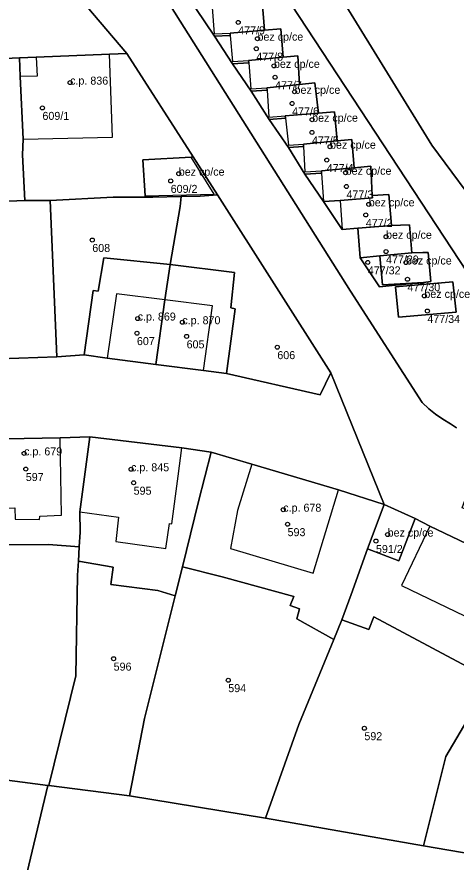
# Model space of a CAD drawing. Extents: x -878211 to -870363, y -1058464 to -1052522.
# Drawn here: x -874333.2 to -874278.3, y -1056644.7 to -1056539.1 of the extents above; entities that cross this region are included whole.
import ezdxf

# ---------------------------------------------------------------- set-up
doc = ezdxf.new("R2010")
doc.units = 0
for name, color, linetype in [('Vrstva 50', 7, 'Continuous'), ('Vrstva 51', 7, 'Continuous'), ('Vrstva 52', 7, 'Continuous')]:
    doc.layers.add(name, color=color, linetype=linetype)

msp = doc.modelspace()

# ---------------------------------------------------------------- linework, layer by layer
at = {"layer": 'Vrstva 50'}
for centre in [(-874305.53, -1056539.80994), (-874303.12, -1056541.83994), (-874303.27, -1056543.09994), (-874301.06, -1056545.23994), (-874326.54, -1056547.32994), (-874300.92, -1056546.66994), (-874298.49, -1056548.47994), (-874330, -1056550.49994), (-874298.79, -1056549.93994), (-874296.29, -1056551.96994), (-874296.31, -1056553.55994), (-874294.05, -1056555.33994), (-874294.46, -1056557.00994), (-874312.96, -1056558.70994), (-874292.1, -1056558.58994), (-874313.97, -1056559.61994), (-874292, -1056560.30994), (-874289.21, -1056562.53994), (-874289.58, -1056563.86994), (-874323.77, -1056566.99994), (-874287.05, -1056566.58994), (-874287.05, -1056568.43994), (-874289.33, -1056569.79994), (-874284.57, -1056569.80994), (-874284.37, -1056571.89994), (-874282.26, -1056573.97994), (-874281.89, -1056575.86994), (-874318.09, -1056576.80994), (-874312.51, -1056577.26994), (-874318.19, -1056578.63994), (-874311.98, -1056579.03994), (-874300.64, -1056580.38994), (-874332.29, -1056593.65994), (-874332.08, -1056595.61994), (-874318.92, -1056595.63994), (-874318.6, -1056597.32994), (-874299.9, -1056600.68994), (-874299.36, -1056602.50994), (-874286.85, -1056603.79994), (-874288.31, -1056604.60994), (-874321.1, -1056619.30994), (-874306.77, -1056621.99994), (-874289.76, -1056627.99994)]:
    msp.add_circle(centre, 0.25, dxfattribs=at)
at = {"layer": 'Vrstva 51'}
for points in [[(-874435.23, -1056399.98), (-874420.12, -1056431.27), (-874417.67, -1056433.88), (-874411.69, -1056441.25), (-874402.98, -1056437.26), (-874396.18, -1056442.04), (-874393, -1056445.85), (-874370.58, -1056484.27), (-874355.24, -1056493.16), (-874347.2, -1056502.65), (-874344.62, -1056505.87), (-874336.73, -1056517.84), (-874326.2, -1056533.69), (-874326.13, -1056535.82), (-874319.45, -1056543.71), (-874311.18, -1056556.62)], [(-874374.27, -1056421.51), (-874364.19, -1056438.09), (-874334.57, -1056483.76), (-874308.37, -1056523.13), (-874269.31, -1056582.53)], [(-874274.54, -1056564.3), (-874281.34, -1056555.14), (-874302.81, -1056520.2), (-874326.64, -1056483.24), (-874328.23, -1056479.69), (-874334.9, -1056469.3), (-874347.77, -1056449.81), (-874358.83, -1056429.38), (-874355.4, -1056424.52)], [(-874269.31, -1056582.53), (-874308.37, -1056523.13), (-874334.57, -1056483.76), (-874364.19, -1056438.09), (-874370.01, -1056432.66), (-874371.12, -1056433.98), (-874373.43, -1056437.7), (-874374.51, -1056440.86), (-874365.05, -1056457.11), (-874357.66, -1056452.3), (-874349.38, -1056465.01), (-874349.37, -1056465.41), (-874354.76, -1056465.71), (-874356.24, -1056463.46), (-874359.52, -1056465.6), (-874291.5, -1056573.37), (-874282.53, -1056587.29), (-874281.7, -1056588.08), (-874280.88, -1056588.76), (-874279.96, -1056589.37), (-874279, -1056589.96), (-874278.23, -1056590.45)], [(-874278.23, -1056590.45), (-874279, -1056589.96), (-874279.96, -1056589.37), (-874280.88, -1056588.76), (-874281.7, -1056588.08), (-874282.53, -1056587.29), (-874291.5, -1056573.37), (-874359.52, -1056465.6)], [(-874302.55, -1056537.15), (-874302.23, -1056540.78), (-874300.2, -1056540.6), (-874299.92, -1056544.15), (-874298.09, -1056544), (-874297.87, -1056547.57), (-874295.97, -1056547.37), (-874295.5, -1056551.13), (-874293.48, -1056550.98), (-874293.17, -1056554.61), (-874291.33, -1056554.45), (-874291.04, -1056557.96), (-874288.96, -1056557.79), (-874288.77, -1056561.43), (-874286.7, -1056561.3), (-874286.38, -1056565.2), (-874284.11, -1056565.08), (-874283.82, -1056568.61), (-874282.45, -1056568.57), (-874281.8, -1056568.54), (-874281.45, -1056572.2), (-874282.39, -1056572.3), (-874285.88, -1056572.65), (-874287.87, -1056572.83), (-874290.29, -1056569.21), (-874290.58, -1056565.53), (-874292.55, -1056565.68), (-874294.87, -1056562.2), (-874297.2, -1056558.77), (-874299.23, -1056555.44), (-874301.67, -1056551.94), (-874303.92, -1056548.41), (-874306.24, -1056544.98), (-874308.51, -1056541.53), (-874310.84, -1056538.07)], [(-874311.18, -1056556.62), (-874308.13, -1056561.37), (-874293.97, -1056583.61), (-874287.3, -1056600.03), (-874283.43, -1056601.8), (-874281.56, -1056602.75), (-874271.47, -1056607.59), (-874266.82, -1056609.82), (-874264.4, -1056605.69), (-874277.53, -1056600.45), (-874276.7, -1056598.17), (-874263.18, -1056603.62), (-874260.74, -1056604.6), (-874243.35, -1056611.56), (-874228.09, -1056617.62), (-874226.05, -1056618.95), (-874224.66, -1056621.19), (-874224.22, -1056623.66), (-874227.16, -1056650.06)], [(-874339.1, -1056591.92), (-874327.78, -1056591.72), (-874324.06, -1056591.59), (-874312.58, -1056592.98), (-874308.91, -1056593.5), (-874303.84, -1056595), (-874293.01, -1056598.21), (-874287.3, -1056600.03), (-874293.97, -1056583.61), (-874295.29, -1056586.33), (-874307.01, -1056583.66), (-874309.88, -1056583.3), (-874315.83, -1056582.54), (-874321.9, -1056581.74), (-874324.8, -1056581.36), (-874328.19, -1056581.59), (-874335.36, -1056581.83)]]:
    msp.add_lwpolyline(points, dxfattribs=at)
for points in [[(-874271.27, -1056564.06), (-874271.86, -1056562.49), (-874272.17, -1056562.59), (-874274.2, -1056556.7), (-874274.34, -1056556.7), (-874275.7, -1056552.64), (-874265.35, -1056549.02), (-874263.86, -1056553.37), (-874265.09, -1056548.95), (-874273.55, -1056514.26), (-874288.39, -1056517.65), (-874302.81, -1056520.2), (-874281.34, -1056555.14), (-874274.54, -1056564.3)], [(-874330.78, -1056544.15), (-874321.63, -1056543.78), (-874319.45, -1056543.71), (-874326.13, -1056535.82), (-874348.38, -1056536.81), (-874364.21, -1056536.96), (-874384.19, -1056537.86), (-874403.14, -1056538.55), (-874419.92, -1056539.28), (-874440.04, -1056540.15), (-874428.62, -1056547.76), (-874417.19, -1056547.36), (-874405.53, -1056546.89), (-874402.16, -1056546.76), (-874383.9, -1056546.09), (-874373.1, -1056545.73), (-874365.49, -1056545.45), (-874362.2, -1056545.35), (-874355.93, -1056545.07), (-874349.64, -1056544.84), (-874344.53, -1056544.62), (-874343.6, -1056544.63), (-874336.58, -1056544.39), (-874332.88, -1056544.22)], [(-874308.79, -1056537.93), (-874310.84, -1056538.07), (-874308.51, -1056541.53), (-874306.54, -1056541.45), (-874306.55, -1056541.15), (-874302.23, -1056540.78), (-874302.55, -1056537.15), (-874304.61, -1056537.26), (-874308.81, -1056537.63)], [(-874302.23, -1056540.78), (-874306.55, -1056541.15), (-874306.54, -1056541.45), (-874308.51, -1056541.53), (-874306.24, -1056544.98), (-874304.22, -1056544.87), (-874304.23, -1056544.57), (-874299.92, -1056544.15), (-874300.2, -1056540.6)], [(-874317.18, -1056561.49), (-874317.46, -1056556.97), (-874311.43, -1056556.63), (-874311.18, -1056556.62), (-874319.45, -1056543.71), (-874321.63, -1056543.78), (-874330.78, -1056544.15), (-874332.88, -1056544.22), (-874332.77, -1056546.58), (-874332.4, -1056554.4), (-874332.5, -1056556.36), (-874332.19, -1056562.08), (-874329.05, -1056562.05), (-874321.16, -1056561.66), (-874317.17, -1056561.66)], [(-874332.4, -1056554.4), (-874332.77, -1056546.58), (-874332.88, -1056544.22), (-874336.58, -1056544.39), (-874343.6, -1056544.63), (-874344.53, -1056544.62), (-874344.44, -1056551.39), (-874344.34, -1056558.31), (-874344.29, -1056562.58), (-874342.16, -1056562.49), (-874332.19, -1056562.08), (-874332.5, -1056556.36)], [(-874304.23, -1056544.57), (-874304.22, -1056544.87), (-874306.24, -1056544.98), (-874303.92, -1056548.41), (-874301.93, -1056548.27), (-874301.95, -1056547.97), (-874297.87, -1056547.57), (-874298.09, -1056544), (-874299.92, -1056544.15)], [(-874297.87, -1056547.57), (-874301.95, -1056547.97), (-874301.93, -1056548.27), (-874303.92, -1056548.41), (-874301.67, -1056551.94), (-874299.62, -1056551.78), (-874299.64, -1056551.48), (-874295.5, -1056551.13), (-874295.97, -1056547.37)], [(-874299.64, -1056551.48), (-874299.62, -1056551.78), (-874301.67, -1056551.94), (-874299.23, -1056555.44), (-874297.38, -1056555.33), (-874297.39, -1056555.03), (-874293.17, -1056554.61), (-874293.48, -1056550.98), (-874295.5, -1056551.13)], [(-874297.38, -1056555.33), (-874299.23, -1056555.44), (-874297.2, -1056558.77), (-874295.11, -1056558.66), (-874295.12, -1056558.36), (-874291.04, -1056557.96), (-874291.33, -1056554.45), (-874293.17, -1056554.61), (-874297.39, -1056555.03)], [(-874308.13, -1056561.37), (-874311.18, -1056556.62), (-874311.43, -1056556.63), (-874317.46, -1056556.97), (-874317.18, -1056561.49), (-874317.17, -1056561.66), (-874316.19, -1056561.66), (-874312.65, -1056561.57), (-874310.3, -1056561.5)], [(-874291.04, -1056557.96), (-874295.12, -1056558.36), (-874295.11, -1056558.66), (-874297.2, -1056558.77), (-874294.87, -1056562.2), (-874292.8, -1056562.06), (-874288.75, -1056561.73), (-874288.77, -1056561.43), (-874288.96, -1056557.79)], [(-874321.16, -1056561.66), (-874329.05, -1056562.05), (-874328.19, -1056581.59), (-874324.8, -1056581.36), (-874323.66, -1056573.29), (-874323.03, -1056573.38), (-874322.34, -1056569.23), (-874314.03, -1056570.04), (-874312.78, -1056562.81), (-874312.65, -1056561.57), (-874316.19, -1056561.66), (-874317.17, -1056561.66)], [(-874308.13, -1056561.37), (-874310.3, -1056561.5), (-874312.65, -1056561.57), (-874312.78, -1056562.81), (-874314.03, -1056570.04), (-874305.99, -1056571.06), (-874306.45, -1056575.48), (-874305.89, -1056575.58), (-874307.01, -1056583.66), (-874295.29, -1056586.33), (-874293.97, -1056583.61)], [(-874286.38, -1056565.2), (-874286.7, -1056561.3), (-874288.77, -1056561.43), (-874288.75, -1056561.73), (-874292.8, -1056562.06), (-874294.87, -1056562.2), (-874292.55, -1056565.68), (-874290.58, -1056565.53)], [(-874329.05, -1056562.05), (-874332.19, -1056562.08), (-874342.16, -1056562.49), (-874341.76, -1056569.18), (-874341.57, -1056573.8), (-874341.5, -1056581.93), (-874335.36, -1056581.83), (-874328.19, -1056581.59)], [(-874283.82, -1056568.61), (-874284.11, -1056565.08), (-874286.38, -1056565.2), (-874290.58, -1056565.53), (-874290.29, -1056569.21), (-874287.84, -1056568.98)], [(-874324.8, -1056581.36), (-874321.9, -1056581.74), (-874315.83, -1056582.54), (-874314.72, -1056574.46), (-874314.03, -1056570.04), (-874322.34, -1056569.23), (-874323.03, -1056573.38), (-874323.66, -1056573.29)], [(-874287.84, -1056568.98), (-874290.29, -1056569.21), (-874287.87, -1056572.83), (-874285.88, -1056572.65), (-874282.39, -1056572.3), (-874287.51, -1056572.58)], [(-874282.39, -1056572.3), (-874281.45, -1056572.2), (-874281.8, -1056568.54), (-874282.45, -1056568.57), (-874283.82, -1056568.61), (-874287.84, -1056568.98), (-874287.51, -1056572.58)], [(-874314.03, -1056570.04), (-874314.72, -1056574.46), (-874315.83, -1056582.54), (-874309.88, -1056583.3), (-874307.01, -1056583.66), (-874305.89, -1056575.58), (-874306.45, -1056575.48), (-874305.99, -1056571.06)], [(-874285.48, -1056576.64), (-874278.3, -1056576.01), (-874278.7, -1056572.22), (-874285.88, -1056572.85)], [(-874285.48, -1056576.64), (-874285.88, -1056572.85), (-874278.7, -1056572.22), (-874278.3, -1056576.01)], [(-874325.4, -1056605.34), (-874325.28, -1056603.5), (-874325.31, -1056600.96), (-874324.06, -1056591.59), (-874327.78, -1056591.72), (-874339.1, -1056591.92), (-874342.02, -1056591.97), (-874341.46, -1056603.51), (-874341.43, -1056606.57), (-874338.56, -1056606.64), (-874338.51, -1056605.07), (-874329.26, -1056605.05)], [(-874325.51, -1056607.14), (-874321.18, -1056607.86), (-874321.47, -1056610.05), (-874315.56, -1056610.79), (-874313.4, -1056611.46), (-874312.48, -1056607.81), (-874310.49, -1056599.68), (-874308.91, -1056593.5), (-874312.58, -1056592.98), (-874324.06, -1056591.59), (-874325.31, -1056600.96), (-874325.28, -1056603.5), (-874325.4, -1056605.34)], [(-874289.39, -1056605.6), (-874287.3, -1056600.03), (-874293.01, -1056598.21), (-874303.84, -1056595), (-874308.91, -1056593.5), (-874310.49, -1056599.68), (-874312.48, -1056607.81), (-874307.54, -1056609.09), (-874298.59, -1056611.53), (-874299.04, -1056612.68), (-874297.89, -1056613.08), (-874298.21, -1056614.32), (-874293.58, -1056616.93), (-874292.56, -1056614.46), (-874291.42, -1056611.29)], [(-874289.39, -1056605.6), (-874285.46, -1056607.09), (-874283.43, -1056601.8), (-874287.3, -1056600.03)], [(-874289.39, -1056605.6), (-874291.42, -1056611.29), (-874292.56, -1056614.46), (-874289.22, -1056615.67), (-874288.59, -1056614.06), (-874273.92, -1056621.91), (-874266.82, -1056609.82), (-874271.47, -1056607.59), (-874281.56, -1056602.75), (-874283.43, -1056601.8), (-874285.46, -1056607.09)], [(-874329.32, -1056635.15), (-874329.19, -1056635.16), (-874325.83, -1056621.47), (-874325.62, -1056608.86), (-874325.51, -1056607.14), (-874325.4, -1056605.34), (-874329.26, -1056605.05), (-874338.51, -1056605.07), (-874338.56, -1056606.64), (-874341.43, -1056606.57), (-874341.39, -1056610.04), (-874341.82, -1056621.41), (-874343.84, -1056632.72), (-874343.94, -1056633.25)], [(-874325.51, -1056607.14), (-874325.62, -1056608.86), (-874325.83, -1056621.47), (-874329.19, -1056635.16), (-874319.13, -1056636.46), (-874317.25, -1056626.77), (-874313.4, -1056611.46), (-874315.56, -1056610.79), (-874321.47, -1056610.05), (-874321.18, -1056607.86)], [(-874312.48, -1056607.81), (-874313.4, -1056611.46), (-874317.25, -1056626.77), (-874319.13, -1056636.46), (-874302.13, -1056639.23), (-874297.97, -1056627.52), (-874293.58, -1056616.93), (-874298.21, -1056614.32), (-874297.89, -1056613.08), (-874299.04, -1056612.68), (-874298.59, -1056611.53), (-874307.54, -1056609.09)], [(-874275.04, -1056623.81), (-874273.92, -1056621.91), (-874288.59, -1056614.06), (-874289.22, -1056615.67), (-874292.56, -1056614.46), (-874293.58, -1056616.93), (-874297.97, -1056627.52), (-874302.13, -1056639.23), (-874282.38, -1056642.67), (-874279.57, -1056631.53)], [(-874247.26, -1056648.43), (-874245.49, -1056648.68), (-874245.44, -1056647.92), (-874244.79, -1056637.85), (-874244.74, -1056637), (-874250.27, -1056636.76), (-874251.77, -1056637.17), (-874253.28, -1056637.11), (-874254.78, -1056636.06), (-874256.54, -1056638.3), (-874267.8, -1056629.43), (-874269.96, -1056632.18), (-874274.95, -1056628.28), (-874272.78, -1056625.56), (-874275.04, -1056623.81), (-874279.57, -1056631.53), (-874282.38, -1056642.67), (-874255.58, -1056647.26)], [(-874329.32, -1056635.15), (-874343.94, -1056633.25), (-874344.23, -1056633.19), (-874347.78, -1056645.9), (-874347.62, -1056645.92), (-874332.58, -1056648.78)], [(-874274.56, -1056658.15), (-874265.9, -1056659.78), (-874257.19, -1056661.29), (-874255.58, -1056647.26), (-874282.38, -1056642.67), (-874302.13, -1056639.23), (-874319.13, -1056636.46), (-874329.19, -1056635.16), (-874329.32, -1056635.15), (-874332.58, -1056648.78), (-874332.38, -1056648.82), (-874317.57, -1056651.26), (-874302.72, -1056653.8), (-874292.57, -1056655.39), (-874283.82, -1056656.58)]]:
    msp.add_lwpolyline(points, close=True, dxfattribs=at)
at = {"layer": 'Vrstva 52'}
for points in [[(-874308.79, -1056537.93), (-874308.53, -1056541.23), (-874306.55, -1056541.15), (-874302.23, -1056540.78), (-874302.55, -1056537.15), (-874304.61, -1056537.26), (-874308.81, -1056537.63)], [(-874306.55, -1056541.15), (-874306.54, -1056541.45), (-874306.26, -1056544.68), (-874304.23, -1056544.57), (-874299.92, -1056544.15), (-874300.2, -1056540.6), (-874302.23, -1056540.78)], [(-874332.4, -1056554.4), (-874321.24, -1056554.15), (-874321.63, -1056543.78), (-874330.78, -1056544.15), (-874330.66, -1056546.51), (-874332.77, -1056546.58)], [(-874304.23, -1056544.57), (-874304.22, -1056544.87), (-874303.95, -1056548.11), (-874301.95, -1056547.97), (-874297.87, -1056547.57), (-874298.09, -1056544), (-874299.92, -1056544.15)], [(-874301.93, -1056548.27), (-874301.69, -1056551.64), (-874299.64, -1056551.48), (-874295.5, -1056551.13), (-874295.97, -1056547.37), (-874297.87, -1056547.57), (-874301.95, -1056547.97)], [(-874299.64, -1056551.48), (-874299.62, -1056551.78), (-874299.26, -1056555.14), (-874297.39, -1056555.03), (-874293.17, -1056554.61), (-874293.48, -1056550.98), (-874295.5, -1056551.13)], [(-874297.39, -1056555.03), (-874297.38, -1056555.33), (-874297.22, -1056558.47), (-874295.12, -1056558.36), (-874291.04, -1056557.96), (-874291.33, -1056554.45), (-874293.17, -1056554.61)], [(-874311.43, -1056556.63), (-874317.46, -1056556.97), (-874317.18, -1056561.49), (-874308.52, -1056561.26)], [(-874288.96, -1056557.79), (-874291.04, -1056557.96), (-874295.12, -1056558.36), (-874295.11, -1056558.66), (-874294.87, -1056562.2), (-874292.8, -1056562.06), (-874288.75, -1056561.73), (-874288.77, -1056561.43)], [(-874288.75, -1056561.73), (-874292.8, -1056562.06), (-874292.55, -1056565.68), (-874290.58, -1056565.53), (-874286.38, -1056565.2), (-874286.7, -1056561.3), (-874288.77, -1056561.43)], [(-874290.58, -1056565.53), (-874290.29, -1056569.21), (-874287.84, -1056568.98), (-874283.82, -1056568.61), (-874284.11, -1056565.08), (-874286.38, -1056565.2)], [(-874283.82, -1056568.61), (-874287.84, -1056568.98), (-874287.51, -1056572.58), (-874282.39, -1056572.3), (-874281.45, -1056572.2), (-874281.8, -1056568.54), (-874282.45, -1056568.57)], [(-874285.88, -1056572.85), (-874285.48, -1056576.64), (-874278.3, -1056576.01), (-874278.7, -1056572.22)], [(-874320.73, -1056573.7), (-874321.9, -1056581.74), (-874315.83, -1056582.54), (-874314.72, -1056574.46)], [(-874308.74, -1056575.21), (-874314.72, -1056574.46), (-874315.83, -1056582.54), (-874309.88, -1056583.3)], [(-874327.78, -1056591.72), (-874339.1, -1056591.92), (-874338.67, -1056600.54), (-874333.43, -1056600.44), (-874333.42, -1056601.87), (-874330.37, -1056601.9), (-874330.34, -1056601.5), (-874327.62, -1056601.36)], [(-874325.31, -1056600.96), (-874320.49, -1056601.62), (-874320.83, -1056604.68), (-874314.57, -1056605.53), (-874314.1, -1056602.42), (-874313.81, -1056602.44), (-874313.02, -1056596.52), (-874312.58, -1056592.98), (-874324.06, -1056591.59)], [(-874306.49, -1056605.56), (-874296.18, -1056608.63), (-874293.01, -1056598.21), (-874303.84, -1056595), (-874305.61, -1056600.8)], [(-874287.3, -1056600.03), (-874289.39, -1056605.6), (-874285.46, -1056607.09), (-874283.43, -1056601.8)], [(-874285.1, -1056610.16), (-874274.98, -1056615.02), (-874271.47, -1056607.59), (-874281.56, -1056602.75)]]:
    msp.add_lwpolyline(points, close=True, dxfattribs=at)

# ---------------------------------------------------------------- texts
at = {"layer": 'Vrstva 50'}
for s, p in [('477/9', (-874305.53, -1056541.299)), ('bez cp/ce', (-874303.12, -1056542.09)), ('477/8', (-874303.27, -1056544.589)), ('bez cp/ce', (-874301.06, -1056545.49)), ('c.p. 836', (-874326.54, -1056547.58)), ('477/7', (-874300.92, -1056548.159)), ('bez cp/ce', (-874298.49, -1056548.73)), ('609/1', (-874330, -1056551.989)), ('477/6', (-874298.79, -1056551.429)), ('bez cp/ce', (-874296.29, -1056552.22)), ('477/5', (-874296.31, -1056555.049)), ('bez cp/ce', (-874294.05, -1056555.59)), ('477/4', (-874294.46, -1056558.499)), ('bez cp/ce', (-874312.96, -1056558.96)), ('bez cp/ce', (-874292.1, -1056558.84)), ('609/2', (-874313.97, -1056561.109)), ('477/3', (-874292, -1056561.799)), ('bez cp/ce', (-874289.21, -1056562.79)), ('477/2', (-874289.58, -1056565.359)), ('bez cp/ce', (-874287.05, -1056566.84)), ('608', (-874323.77, -1056568.489)), ('477/29', (-874287.05, -1056569.929)), ('bez cp/ce', (-874284.57, -1056570.06)), ('477/32', (-874289.33, -1056571.289)), ('477/30', (-874284.37, -1056573.389)), ('bez cp/ce', (-874282.26, -1056574.23)), ('c.p. 869', (-874318.09, -1056577.06)), ('c.p. 870', (-874312.51, -1056577.52)), ('477/34', (-874281.89, -1056577.359)), ('607', (-874318.19, -1056580.129)), ('605', (-874311.98, -1056580.529)), ('606', (-874300.64, -1056581.879)), ('c.p. 679', (-874332.29, -1056593.909)), ('c.p. 845', (-874318.92, -1056595.889)), ('597', (-874332.08, -1056597.109)), ('595', (-874318.6, -1056598.819)), ('c.p. 678', (-874299.9, -1056600.94)), ('593', (-874299.36, -1056603.999)), ('bez cp/ce', (-874286.85, -1056604.05)), ('591/2', (-874288.31, -1056606.099)), ('596', (-874321.1, -1056620.799)), ('594', (-874306.77, -1056623.489)), ('592', (-874289.76, -1056629.489))]:
    msp.add_text(s, height=0.999996, dxfattribs=at).set_placement(p)

doc.saveas('drawing.dxf')
